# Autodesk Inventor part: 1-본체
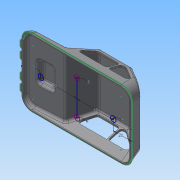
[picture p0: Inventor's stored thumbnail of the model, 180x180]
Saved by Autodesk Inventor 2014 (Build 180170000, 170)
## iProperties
Created: 2015-05
Part Number: 1-본체
Material: Generic
Document SubType Name: Modeling
Designer: Administrator
Density: 1 g/cm^3
Appearance: Default
Author: Administrator
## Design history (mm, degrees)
sketch "스케치1"
  geometry: L1 (-61, 0)-(61, 0); L2 (-61, 0)-(-59.66, 5); L3 (-59.66, 5)-(-19, 7.131); L4 (-4.71, 30)-(61, 30); L5 (-19, 7.131)-(-4.71, 30); L6 (61, 0)-(61, 30); 2 further points
  constraints: 12 end point, 2 coincident, 1 horizontal, 1 midpoint, 1 parallel, 1 perpendicular
  dimensions: "d9" = 3 deg angle of L1 L3; "d11" = 105 deg angle of L1 L2; "d12" = 125 deg angle of L5 L3; "d16" = 30 distance between parallel lines of L1 L4; "d18" = 5 distance from line of L1 L2.end; "d40" = 122 distance of L1.start L1.end; "d70" = 42 horizontal distance of L3.end L1.start
extrude "돌출1" new body sketch "스케치1" distance "d19" = 76; taper "d20" = 0 deg
sketch "스케치7"
  geometry: L1 (61, 0)-(61, 30) reference; L2 (61, 30)-(-4.71, 30) reference; L3 (31, 30)-(61, 10); 1 further point
  constraints: 2 end point, 2 point on line
  dimensions: "d41" = 30 horizontal distance of L3.start L3.end; "d42" = 20 vertical distance of L3.start L3.end
extrude "돌출6" cut sketch "스케치7" stored distance "d43" = 1; taper "d44" = 0 deg
sketch "스케치8"
  geometry: L1 (61, 10)-(31, 30) reference; L2 (61, 0)-(61, 10) reference; L3 (61, 0)-(57.738, 12.175); 1 further point
  constraints: 2 end point, 1 point on line
  dimensions: "d45" = 15 deg angle of L2 L3
extrude "돌출7" cut sketch "스케치8" stored distance "d46" = 1; taper "d47" = 0 deg
sketch "스케치9"
  geometry: L1 (12.175, 76)-(12.175, 0) reference; L2 (30, 0)-(12.175, 0) reference; L3 (30, 76)-(30, 0) reference; L4 (12.175, 76)-(30, 76) reference; L5 (0, 76)-(12.175, 76) reference; L6 (12.175, 0)-(0, 0) reference; L7 (0, 0)-(0, 76) reference; L8 (0, 76)-(30, 67.962); L9 (0, 0)-(30, 8.038)
  constraints: 4 end point, 2 point on line
  dimensions: "d48" = 15 deg angle of L4 L8; "d49" = 15 deg angle of L2 L9
extrude "돌출8" cut sketch "스케치9" stored distance "d50" = 1; taper "d51" = 0 deg
sketch "스케치10"
  geometry: L1 (0, 73.321)-(0, 0) reference; L2 (11, 23.66)-(31, 23.66); L3 (31, 23.66)-(31, 49.66); L4 (31, 49.66)-(11, 49.66); L5 (11, 49.66)-(11, 23.66); 3 further points
  constraints: 8 end point, 2 midpoint, 2 parallel, 1 horizontal, 1 horizontal alignment, 1 perpendicular
  dimensions: "d52" = 20 distance of L2.start L2.end; "d53" = 26 distance of L4.end L2.start; "d54" = 11 distance between parallel lines of L5 L1
extrude "돌출9" join sketch "스케치10" distance "d55" = 5; taper "d56" = -20 deg
fillet "모깎기3" dims "d92" = 12
feature "쉘2" dims "d58" = 2
sketch "스케치12"
  geometry: L1 (11.73, 73.929)-(110.27, 73.929) reference; 2 further points; 1 other entity
  constraints: 1 other
sketch "스케치19"
  geometry: L1 (98.679, 2.071)-(0.139, 2.071) reference; L2 (-9.521, 11.73)-(-9.521, 64.27) reference; L3 (0.139, 73.929)-(98.679, 73.929) reference; L4 (108.338, 64.27)-(108.338, 11.73) reference; L5 (98.679, 74.929)-(0.139, 74.929); L6 (-10.521, 64.27)-(-10.521, 11.73); L7 (0.139, 1.071)-(98.679, 1.071); L8 (109.338, 11.73)-(109.338, 64.27); 5 further points; 4 other entities
  constraints: 8 end point, 7 parallel, 16 other
  dimensions: "d93" = 1 distance between parallel lines of L5 L3
extrude "돌출14" join sketch "스케치19" distance "d94" = 1; taper "d95" = 0 deg
sketch "스케치14"
  geometry: L1 (-19, 7.131)-(-4.71, 30) reference; L2 (-4.71, 30)-(31, 30) reference; L3 (31, 30)-(57.738, 12.175) reference; L4 (57.738, 12.175)-(61, 0) reference; L5 (51.986, 10)-(29.486, 25); L6 (-1.938, 25)-(-11.311, 10); L7 (22.689, 10)-(22.689, 25); L8 (23.986, 10)-(23.986, 25); L9 (29.486, 25)-(23.986, 25); L10 (22.689, 25)-(-1.938, 25); L11 (-11.311, 10)-(22.689, 10); L12 (23.986, 10)-(51.986, 10); 1 further point
  constraints: 16 end point, 5 parallel, 2 perpendicular
  dimensions: "d65" = 5 distance between parallel lines of L3 L5; "d66" = 5 distance between parallel lines of L1 L6; "d68" = 28 distance from line of L5.start L8; "d69" = 34 distance from line of L6.end L7; "d71" = 5 distance between parallel lines of L2 L10; "d72" = 15 distance between parallel lines of L11 L10; "d73" = 5 distance between parallel lines of L2 L9; "d74" = 15 distance of L8.start L8.end
extrude "돌출11" cut sketch "스케치14" stored distance "d75" = 1; taper "d76" = 0 deg
fillet "모깎기4" dims "d96" = 3
fillet "모깎기5" dims "d97" = 3
fillet "모깎기6" dims "d98" = 3
node "작업 평면5"
  node "작업 평면4"
sketch "스케치20"
  geometry: L1 (0, 11.591)-(0, 0) reference; L2 (0, -36.409)-(0, -16.409); L3 (0, -51.409)-(0, -43.409); L4 (0, -40.409)-(0, -36.409); L5 (0, -16.409)-(0, -12.409); L6 (0, -9.409)-(0, -1.409); A1 r 4 centre (0, -16.409) between (0, -12.409) and (0, -20.409); A2 r 4 centre (0, -36.409) between (0, -32.409) and (0, -40.409); A3 r 4 centre (0, -47.409) between (0, -43.409) and (0, -51.409); A4 r 4 centre (0, -5.409) between (0, -1.409) and (0, -9.409); 2 further points
  constraints: 10 end point, 8 point on circle, 4 centre point, 4 vertical, 3 equal radius, 2 coincident, 1 collinear, 1 midpoint, 12 other
  dimensions: "d100" = 20 distance of L2.start L2.end; "d101" = 8 diameter of A1; "d102" = 11 distance of L2.start A3.centre; "d103" = 11 distance of L2.end A4.centre
extrude "돌출15" join sketch "스케치20" stored distance "d104" = 1; taper "d105" = 0 deg
chamfer "모따기1" distance "d106" = 1; stored, may be unused: second distance "d107" = 2, angle "d108" = 45 deg
sketch "스케치21"
  geometry: L1 (64.047, -1.251)-(64.047, -54.068) reference; 3 further points
  constraints: 1 horizontal alignment, 1 midpoint, 1 other
  dimensions: "d109" = 50 distance from line of point (14.047, -27.66) L1
feature "엠보싱1" sketch "스케치21" dims "d110" = 0.5, "d111" = 0
sketch "스케치23"
  geometry: L1 (-13.591, 62)-(-12.591, 63) reference; L2 (-13.591, 56)-(-13.591, 62) reference; L3 (-12.591, 55)-(-13.591, 56) reference; L4 (-12.591, 55)-(-11.591, 55) reference; L5 (-11.591, 52)-(-11.591, 55) reference; L6 (-12.591, 52)-(-11.591, 52) reference; L7 (-13.591, 51)-(-12.591, 52) reference; L8 (-13.591, 45)-(-13.591, 51) reference; L9 (-12.591, 44)-(-13.591, 45) reference; L10 (-12.591, 44)-(-11.591, 44) reference; L11 (-11.591, 32)-(-11.591, 44) reference; L12 (-12.591, 32)-(-11.591, 32) reference; L13 (-13.591, 31)-(-12.591, 32) reference; L14 (-13.591, 25)-(-13.591, 31) reference; L15 (-12.591, 24)-(-13.591, 25) reference; L16 (-12.591, 24)-(-11.591, 24) reference; L17 (-11.591, 21)-(-11.591, 24) reference; L18 (-12.591, 21)-(-11.591, 21) reference; L19 (-13.591, 20)-(-12.591, 21) reference; L20 (-13.591, 14)-(-13.591, 20) reference; L21 (-12.591, 13)-(-13.591, 14) reference; L22 (-12.591, 13)-(-11.591, 13) reference; L23 (-11.591, 11.591)-(-11.591, 13) reference; L24 (0, 0)-(98.818, 0) reference; L25 (110.409, 11.591)-(110.409, 64.409) reference; L26 (0, 76)-(98.818, 76) reference; L27 (-11.591, 63)-(-11.591, 64.409) reference; L28 (-12.591, 63)-(-11.591, 63) reference; L29 (109.338, 64.27)-(109.338, 11.73) reference; L30 (98.679, 1.071)-(0.139, 1.071) reference; L31 (-10.521, 11.73)-(-10.521, 64.27) reference; L32 (0.139, 74.929)-(98.679, 74.929) reference; L33 (109.338, 11.73)-(109.338, 64.27) reference; L34 (49.409, 57.137)-(49.409, 19.022); C1 r 3 at (9.409, 38); C2 r 3 at (49.409, 57.137); C3 r 3 at (49.409, 19.022); C4 r 3 at (89.409, 38); 7 further points; 4 other entities
  constraints: 4 centre point, 2 end point, 2 horizontal alignment, 2 midpoint, 1 parallel, 8 other
  dimensions: "d118" = 21 distance from line of L25 C4.centre; "d119" = 40 distance from line of C4.centre L34; "d120" = 40 distance from line of C1.centre L34; "d121" = 6 diameter of C2; "d122" = 6 diameter of C3; "d123" = 6 diameter of C4; "d124" = 6 diameter of C1
node "솔리드1"
node "투영된 루프3"
other parameters: "d63" = 5, "d64" = 15, "d67" = 15, "d99" = -2
